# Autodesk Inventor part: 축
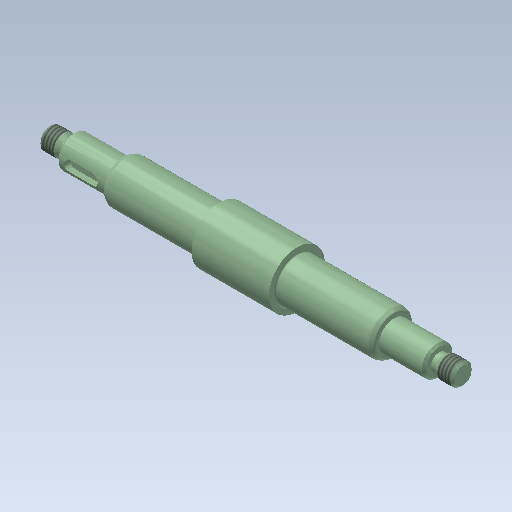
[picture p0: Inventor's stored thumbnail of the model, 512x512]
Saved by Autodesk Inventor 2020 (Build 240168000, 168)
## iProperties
Created: 2011-02
Part Number: 축
Document SubType Name: Modeling
Designer: pww
Density: 1 g/cm^3
Material: 강철, 연강
Appearance: 강철(1)
Author: pww
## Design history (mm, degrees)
sketch "스케치1"
  geometry: L1 (0, 0)-(192, 0); L2 (0, 0)-(0, 5); L3 (0, 5)-(7.008, 5); L4 (9, 3.85)-(11, 3.85); L5 (11, 3.85)-(11, 7.5); L6 (11, 7.5)-(34, 7.5); L7 (34, 7.5)-(34, 8.273); L8 (36.528, 10)-(78.4, 10); L9 (79, 10.6)-(79, 13); L10 (79, 13)-(115, 13); L11 (115, 13)-(115, 10.6); L12 (115.6, 10)-(157.472, 10); L13 (160, 8.273)-(160, 7); L14 (160, 7)-(181, 7); L15 (181, 7)-(181, 3.85); L16 (181, 3.85)-(183, 3.85); L17 (184.992, 5)-(192, 5); L18 (192, 5)-(192, 0); L19 (79, 22.9)-(79, -22.9) reference; L20 (115, 22.9)-(115, -22.9) reference; L21 (9, 3.85)-(7.008, 5); L22 (183, 3.85)-(184.992, 5); L23 (34.5, 9.139)-(35.528, 9.732); L24 (159.5, 9.139)-(158.472, 9.732); A1 r 0.6 centre (78.4, 10.6) between (78.4, 10) and (79, 10.6); A2 r 0.6 centre (115.6, 10.6) between (115, 10.6) and (115.6, 10); A3 r 2 centre (36.528, 8) between (36.528, 10) and (35.528, 9.732); A4 r 1 centre (35, 8.273) between (34.5, 9.139) and (34, 8.273); A5 r 1 centre (159, 8.273) between (160, 8.273) and (159.5, 9.139); A6 r 2 centre (157.472, 8) between (158.472, 9.732) and (157.472, 10); 5 further points
  constraints: 44 end point, 12 point on circle, 12 tangent, 10 parallel, 10 point on line, 6 centre point, 6 perpendicular, 4 collinear, 2 horizontal, 1 equal radius
  dimensions: "d0" = 192 distance of L1.start L1.end; "d1" = 10 diameter of L3 L1; "d3" = 7.7 diameter of L4 L1; "d4" = 2 distance of L4.start L4.end; "d5" = 15 diameter of L6 L1; "d6" = 23 distance of L5.end L6.end; "d7" = 20 diameter of L8 L1; "d10" = 10 diameter of L17 L1; "d12" = 2 distance of L15.end L16.end; "d13" = 21 distance of L13.end L14.end; "d14" = 11 distance between parallel lines of L18 L15; "d15" = 14 diameter of L14 L1; "d35" = 11 distance between parallel lines of L5 L2; "d36" = 3 distance between parallel lines of L10 L8; "d37" = 0.6 radius of A1; "d39" = 30 deg angle of L21 L4; "d40" = 30 deg angle of L22 L16; "d42" = 30 deg angle of L8 L23; "d43" = 17.7 diameter of point (34, 8.85) L1; "d44" = 2 radius of A3; "d45" = 1 radius of A4; "d46" = 30 deg angle of L12 L24; "d47" = 17.7 diameter of point (160, 8.85) L1; "d48" = 1 radius of A5; "d49" = 2 radius of A6
revolve "회전1" sketch "스케치1" stored, may be unused: angle "d17" = 90 deg
feature "스레드1" dims "d18" = 10, "d19" = 0
feature "스레드2" dims "d20" = 10, "d21" = 0
chamfer "모따기1" distance "d22" = 1; stored, may be unused: second distance "d23" = 2, angle "d24" = 45 deg
node "작업 평면1"
sketch "스케치2"
  geometry: L1 (-6, 2.5)-(5, 2.5); L2 (5, -2.5)-(-6, -2.5); L3 (11.5, -8.273)-(11.5, 8.273) reference; A1 r 2.5 centre (5, 0) between (5, -2.5) and (5, 2.5); A2 r 2.5 centre (-6, 0) between (-6, 2.5) and (-6, -2.5); 1 further point
  constraints: 4 end point, 4 point on circle, 4 tangent, 2 centre point, 1 horizontal, 1 horizontal alignment, 1 parallel
  dimensions: "d25" = 5 distance between parallel lines of L2 L1; "d27" = 16 dimension on A1 A2; "d50" = 4 distance edge to line of A1 L3
extrude "돌출1" cut sketch "스케치2" distance "d28" = 3; taper "d29" = 0 deg
node "작업 평면2"
sketch "스케치3"
  geometry: L1 (-5, 2.5)-(6, 2.5); L2 (6, -2.5)-(-5, -2.5); L3 (-10.5, -6)-(-10.5, 6) reference; A1 r 2.5 centre (6, 0) between (6, -2.5) and (6, 2.5); A2 r 2.5 centre (-5, 0) between (-5, 2.5) and (-5, -2.5); 1 further point
  constraints: 4 end point, 4 point on circle, 4 tangent, 2 centre point, 1 horizontal, 1 horizontal alignment, 1 parallel
  dimensions: "d30" = 3 distance edge to line of A2 L3; "d31" = 5 distance between parallel lines of L2 L1; "d32" = 16 dimension on A1 A2
extrude "돌출2" cut sketch "스케치3" distance "d33" = 3; taper "d34" = 0 deg
node "솔리드1"
node "참조1"
node "참조2"
